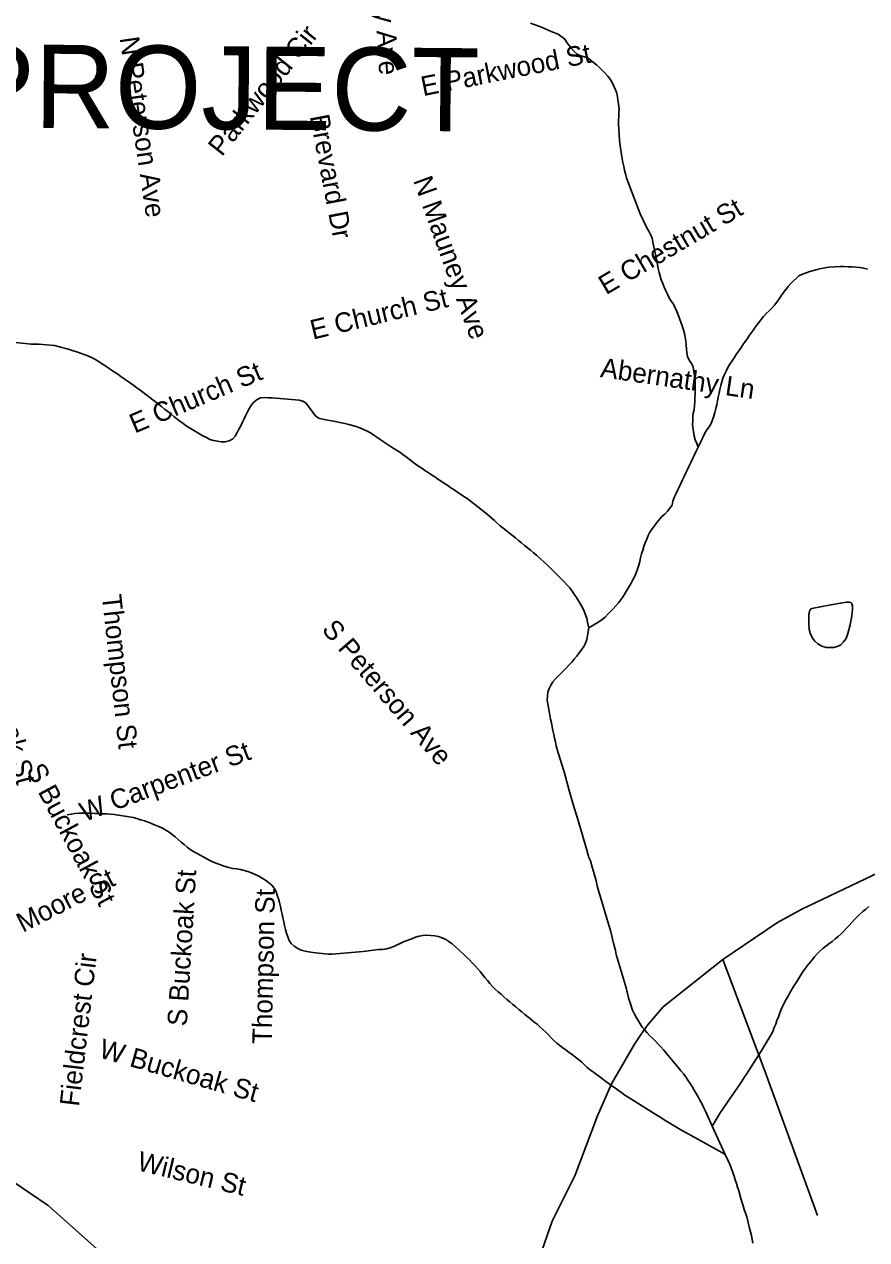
# Model space of a CAD drawing. Extents: x 1379453 to 1387082, y 594364 to 596664.
# Drawn here: x 1380505.6 to 1380647.4, y 596071.5 to 596276.1 of the extents above; entities that cross this region are included whole.
import ezdxf

# ---------------------------------------------------------------- set-up
doc = ezdxf.new("R2010")
doc.units = 0
for name, color, linetype in [('Old_Level_10', 7, 'Continuous'), ('Old_Level_11', 7, 'Continuous'), ('Old_Level_31', 7, 'Continuous'), ('Old_Level_32', 7, 'Continuous'), ('Old_Level_35', 7, 'Continuous'), ('Old_Level_50', 7, 'Continuous'), ('Old_Level_59', 7, 'Continuous'), ('Old_Level_62', 7, 'Continuous')]:
    doc.layers.add(name, color=color, linetype=linetype)

msp = doc.modelspace()

# ---------------------------------------------------------------- linework, layer by layer
at = {"layer": 'Old_Level_31'}
msp.add_line((1380606.68, 596105.29), (1380606.68, 596105.29), dxfattribs=at)
at = {"layer": 'Old_Level_32'}
for points in [[(1380690.45, 596156.89), (1380689.31, 596155.05), (1380687.19, 596153.09), (1380684.16, 596150.95), (1380678.29, 596147.37), (1380650.57, 596133.86), (1380636.43, 596127.15), (1380632.33, 596124.88), (1380623.16, 596118.7), (1380613.12, 596110.73), (1380610.48, 596107.63), (1380609.3, 596105.92)], [(1380609.3, 596105.92), (1380608.29, 596104.44), (1380604.42, 596097.75), (1380602.03, 596092.34), (1380598.21, 596082.26), (1380594.44, 596074.6), (1380592.23, 596068.33)], [(1380520.37, 596067.67), (1380509.57, 596077.25), (1380500.59, 596083.35)]]:
    msp.add_lwpolyline(points, dxfattribs=at)
at = {"layer": 'Old_Level_35'}
msp.add_lwpolyline([(1380639.09, 596075.58), (1380630.27, 596099.77), (1380623.16, 596118.7)], dxfattribs=at)
at = {"layer": 'Old_Level_50'}
msp.add_line((1380609.48, 596106.26), (1380609.48, 596106.26), dxfattribs=at)
at = {"layer": 'Old_Level_59'}
msp.add_line((1380621.38, 596090.59), (1380623.55, 596085.85), dxfattribs=at)
for points in [[(1380600.61, 596174.49), (1380600.37, 596173.19), (1380600.23, 596172.55), (1380600.05, 596171.92), (1380599.74, 596171.34), (1380599.36, 596170.81), (1380598.97, 596170.28), (1380598.57, 596169.76), (1380598.15, 596169.25), (1380597.72, 596168.75), (1380597.29, 596168.26), (1380596.84, 596167.79), (1380596.37, 596167.32), (1380595.91, 596166.85), (1380595.45, 596166.38), (1380595, 596165.91), (1380594.56, 596165.42), (1380594.18, 596164.88), (1380593.9, 596164.29), (1380593.7, 596163.66), (1380593.61, 596163.01), (1380593.59, 596162.35), (1380593.7, 596161.71), (1380594.03, 596159.79), (1380594.15, 596159.14), (1380594.28, 596158.5), (1380594.41, 596157.85), (1380594.55, 596157.21), (1380594.68, 596156.57), (1380594.82, 596155.93), (1380594.97, 596155.29), (1380595.12, 596154.65), (1380595.27, 596154.01), (1380596.04, 596151.5), (1380596.45, 596150.26), (1380597.29, 596147.12), (1380598.02, 596144.6), (1380598.78, 596142.09), (1380599.55, 596139.6), (1380600.24, 596137.09), (1380600.6, 596135.85), (1380600.86, 596135.26), (1380601.22, 596134.02), (1380601.76, 596132.13), (1380602.07, 596130.86), (1380603.18, 596127.09), (1380604.29, 596123.34), (1380604.76, 596121.44), (1380605.07, 596120.18), (1380605.21, 596119.54), (1380606.86, 596113.9), (1380607.33, 596112.02), (1380607.55, 596111.4), (1380607.97, 596110.17), (1380608.25, 596109.58), (1380608.56, 596108.99), (1380608.89, 596108.42), (1380609.22, 596107.86), (1380609.59, 596107.31), (1380610, 596106.8), (1380610.44, 596106.31), (1380610.89, 596105.84), (1380611.35, 596105.37), (1380611.82, 596104.9), (1380612.28, 596104.43), (1380612.73, 596103.96), (1380613.17, 596103.47), (1380615.7, 596100.46), (1380616.11, 596099.96), (1380616.52, 596099.45), (1380616.9, 596098.91), (1380617.28, 596098.37), (1380617.63, 596097.82), (1380617.98, 596097.27), (1380618.32, 596096.7), (1380618.65, 596096.14), (1380618.98, 596095.56), (1380619.3, 596094.99), (1380619.61, 596094.41), (1380619.9, 596093.83), (1380620.18, 596093.24), (1380620.46, 596092.64), (1380621.38, 596090.59)], [(1380623.55, 596085.85), (1380624.1, 596084.66), (1380624.36, 596084.06), (1380624.6, 596083.45), (1380624.82, 596082.83), (1380625.04, 596082.21), (1380625.25, 596081.59), (1380625.46, 596080.96), (1380625.65, 596080.34), (1380625.84, 596079.71), (1380626.18, 596078.46), (1380626.55, 596077.22), (1380626.74, 596076.6), (1380626.99, 596075.98), (1380627.17, 596075.36), (1380627.67, 596073.47), (1380627.83, 596072.84), (1380627.97, 596072.19), (1380628.1, 596071.55), (1380628.22, 596070.9)]]:
    msp.add_lwpolyline(points, dxfattribs=at)
at = {"layer": 'Old_Level_62'}
for points in [[(1380600.49, 596270.38), (1380599.87, 596270.6), (1380599.23, 596270.8), (1380598.64, 596271.09), (1380598.13, 596271.51), (1380597.7, 596272.01), (1380597.29, 596272.52), (1380596.9, 596273.04), (1380596.57, 596273.61), (1380595.41, 596274.42), (1380594.26, 596274.9), (1380592.64, 596275.6), (1380590.8, 596276.31)], [(1380618.98, 596204.89), (1380618.75, 596205.51), (1380618.52, 596206.13), (1380618.34, 596206.75), (1380618.07, 596208.68), (1380618.09, 596209.34), (1380618.12, 596210), (1380618.17, 596210.65), (1380618.34, 596211.28), (1380618.39, 596211.94), (1380618.42, 596212.59), (1380618.45, 596213.25), (1380618.47, 596213.91), (1380618.49, 596214.56), (1380618.49, 596215.22), (1380618.49, 596215.87), (1380618.43, 596216.53), (1380618.17, 596218.44), (1380617.85, 596219), (1380617.49, 596219.57), (1380617.22, 596220.16), (1380617.09, 596220.8), (1380617.02, 596221.45), (1380616.98, 596222.11), (1380616.93, 596222.77), (1380616.83, 596223.42), (1380616.69, 596224.06), (1380616.51, 596224.69), (1380616.32, 596225.32), (1380616.11, 596225.94), (1380615.88, 596226.56), (1380615.65, 596227.18), (1380615.39, 596227.78), (1380615.12, 596228.38), (1380614.84, 596228.97), (1380614.48, 596229.52), (1380614.13, 596230.07), (1380613.83, 596230.66), (1380613.55, 596231.25), (1380613.28, 596231.85), (1380613.03, 596232.46), (1380612.79, 596233.07), (1380612.58, 596233.69), (1380612.41, 596234.33), (1380612.26, 596234.97), (1380612.14, 596235.61), (1380612.02, 596236.26), (1380611.64, 596238.16), (1380611.37, 596239.45), (1380611.23, 596240.09), (1380610.99, 596240.69), (1380610.69, 596241.28), (1380610.36, 596241.86), (1380609.26, 596244.19), (1380607.18, 596249.66), (1380606.96, 596250.27), (1380606.78, 596250.91), (1380606.61, 596251.54), (1380606.46, 596252.18), (1380606.32, 596252.82), (1380606.19, 596253.47), (1380605.82, 596256.03), (1380605.76, 596256.67), (1380605.57, 596259.27), (1380605.59, 596259.92), (1380605.62, 596260.58), (1380605.66, 596261.24), (1380605.68, 596261.89), (1380605.43, 596263.84), (1380605.32, 596264.48), (1380605.1, 596265.09), (1380604.83, 596265.69), (1380604.52, 596266.28), (1380604.18, 596266.84), (1380603.8, 596267.37), (1380603.37, 596267.87), (1380602.9, 596268.33), (1380602.42, 596268.78), (1380601.92, 596269.21), (1380600.49, 596270.38)], [(1380618.98, 596204.89), (1380619.54, 596206.08), (1380619.82, 596206.68), (1380620.11, 596207.26), (1380620.45, 596207.82), (1380620.84, 596208.36), (1380621.17, 596208.92), (1380621.41, 596209.53), (1380621.63, 596210.15), (1380621.82, 596210.78), (1380622, 596211.42), (1380622.15, 596212.05), (1380622.28, 596212.69), (1380622.39, 596213.34), (1380622.51, 596213.99), (1380622.66, 596214.63), (1380622.82, 596215.27), (1380622.98, 596215.91), (1380623.18, 596216.53), (1380623.42, 596217.14), (1380623.7, 596217.73), (1380624.01, 596218.31), (1380624.34, 596218.88), (1380624.7, 596219.44), (1380625.05, 596219.98), (1380625.42, 596220.53), (1380625.79, 596221.07), (1380626.16, 596221.61), (1380626.53, 596222.16), (1380626.91, 596222.7), (1380627.29, 596223.23), (1380627.67, 596223.77), (1380628.05, 596224.3), (1380628.43, 596224.84), (1380628.82, 596225.37), (1380629.2, 596225.9), (1380629.6, 596226.42), (1380629.99, 596226.94), (1380630.44, 596227.43), (1380630.93, 596227.86), (1380631.41, 596228.31), (1380631.83, 596228.81), (1380632.23, 596229.34), (1380632.62, 596229.87), (1380633, 596230.4), (1380633.38, 596230.94), (1380633.77, 596231.46), (1380634.18, 596231.98), (1380634.62, 596232.46), (1380635.95, 596233.75), (1380636.55, 596234.02), (1380637.16, 596234.26), (1380637.78, 596234.49), (1380638.41, 596234.68), (1380639.04, 596234.85), (1380639.69, 596234.99), (1380640.33, 596235.12), (1380640.98, 596235.22), (1380642.93, 596235.32), (1380643.58, 596235.31), (1380644.24, 596235.3), (1380644.9, 596235.28), (1380645.56, 596235.24), (1380646.21, 596235.17), (1380646.86, 596235.06), (1380647.49, 596234.87)], [(1380504.13, 596222.52), (1380506.71, 596222.27), (1380507.37, 596222.25), (1380508.03, 596222.25), (1380508.68, 596222.22), (1380510.62, 596222.01), (1380511.26, 596221.88), (1380511.89, 596221.72), (1380512.52, 596221.55), (1380513.15, 596221.36), (1380513.78, 596221.16), (1380514.4, 596220.96), (1380515.03, 596220.75), (1380515.65, 596220.53), (1380516.26, 596220.28), (1380516.86, 596220.01), (1380517.43, 596219.71), (1380518, 596219.37), (1380518.56, 596219.02), (1380519.1, 596218.66), (1380519.65, 596218.29), (1380520.19, 596217.92), (1380520.74, 596217.55), (1380521.27, 596217.18), (1380521.81, 596216.81), (1380522.35, 596216.43), (1380522.89, 596216.06), (1380523.43, 596215.68), (1380523.97, 596215.3), (1380524.5, 596214.92), (1380525.04, 596214.54), (1380527.64, 596212.56), (1380528.16, 596212.16), (1380528.67, 596211.75), (1380529.18, 596211.34), (1380529.7, 596210.92), (1380530.21, 596210.51), (1380530.72, 596210.1), (1380531.24, 596209.7), (1380531.76, 596209.3), (1380532.28, 596208.9), (1380532.82, 596208.52), (1380533.36, 596208.16), (1380533.92, 596207.82), (1380534.49, 596207.48), (1380535.05, 596207.15), (1380535.63, 596206.83), (1380536.21, 596206.52), (1380536.79, 596206.23), (1380537.42, 596206.02), (1380538.06, 596205.9), (1380538.72, 596205.8), (1380539.37, 596205.82), (1380540.02, 596205.98), (1380540.58, 596206.29), (1380541.03, 596206.79), (1380541.37, 596207.36), (1380541.68, 596207.93), (1380541.98, 596208.52), (1380542.27, 596209.11), (1380542.56, 596209.7), (1380542.85, 596210.29), (1380543.15, 596210.88), (1380543.45, 596211.46), (1380543.78, 596212.02), (1380544.21, 596212.51), (1380544.74, 596212.92), (1380545.34, 596213.2), (1380545.99, 596213.25), (1380546.65, 596213.24), (1380547.3, 596213.21), (1380551.19, 596212.91), (1380551.84, 596212.85), (1380552.47, 596212.65), (1380553.01, 596212.31), (1380553.41, 596211.79), (1380553.79, 596211.25), (1380554.16, 596210.71), (1380554.55, 596210.18), (1380555.08, 596209.79), (1380556.33, 596209.52), (1380557.62, 596209.32), (1380559.53, 596208.92), (1380560.17, 596208.76), (1380560.81, 596208.59), (1380561.43, 596208.38), (1380562.04, 596208.15), (1380562.66, 596207.9), (1380563.25, 596207.63), (1380563.82, 596207.31), (1380564.37, 596206.95), (1380564.92, 596206.58), (1380565.45, 596206.2), (1380567.64, 596204.75), (1380568.21, 596204.42), (1380568.75, 596204.06)], [(1380568.75, 596204.06), (1380569.3, 596203.69), (1380569.83, 596203.31), (1380570.33, 596202.89), (1380570.84, 596202.48), (1380571.38, 596202.11), (1380571.93, 596201.74), (1380572.47, 596201.37), (1380573.01, 596201.01), (1380573.56, 596200.64), (1380574.1, 596200.28), (1380574.65, 596199.92), (1380575.19, 596199.55), (1380575.74, 596199.19), (1380576.29, 596198.82), (1380576.83, 596198.46), (1380577.38, 596198.09), (1380577.92, 596197.72), (1380578.47, 596197.36), (1380579.01, 596196.99), (1380579.55, 596196.62), (1380580.09, 596196.25), (1380580.63, 596195.87), (1380583.2, 596193.84), (1380584.7, 596192.57), (1380585.18, 596192.12), (1380585.69, 596191.7), (1380586.19, 596191.28), (1380586.7, 596190.87), (1380587.21, 596190.45), (1380587.72, 596190.04), (1380588.23, 596189.63), (1380588.75, 596189.21), (1380589.25, 596188.8), (1380589.76, 596188.39), (1380590.27, 596187.97), (1380590.78, 596187.56), (1380591.28, 596187.14), (1380591.78, 596186.71), (1380593.73, 596184.96), (1380596.49, 596182.19), (1380596.94, 596181.71), (1380597.37, 596181.21), (1380597.77, 596180.69), (1380598.15, 596180.15), (1380598.52, 596179.6), (1380598.87, 596179.05), (1380599.21, 596178.49), (1380599.54, 596177.92), (1380599.83, 596177.33), (1380600.06, 596176.72), (1380600.24, 596176.09), (1380600.39, 596175.45), (1380600.61, 596174.49)], [(1380600.61, 596174.49), (1380601.74, 596175.16), (1380602.3, 596175.51), (1380602.82, 596175.89), (1380603.32, 596176.32), (1380603.79, 596176.78), (1380604.26, 596177.25), (1380604.71, 596177.72), (1380605.15, 596178.21), (1380605.56, 596178.72), (1380605.97, 596179.24), (1380606.35, 596179.77), (1380606.7, 596180.33), (1380607.04, 596180.89), (1380607.38, 596181.46), (1380607.7, 596182.03), (1380608.01, 596182.61), (1380608.31, 596183.19), (1380608.57, 596183.79), (1380608.81, 596184.4), (1380608.99, 596185.03), (1380609.16, 596185.67), (1380609.31, 596186.3), (1380609.48, 596186.94), (1380609.66, 596187.57), (1380609.88, 596188.19), (1380610.09, 596188.82), (1380610.33, 596189.44), (1380610.59, 596190.04), (1380610.89, 596190.62), (1380611.24, 596191.17), (1380611.63, 596191.7), (1380612.04, 596192.21), (1380612.89, 596193.22), (1380613.38, 596193.64), (1380613.81, 596194.14), (1380614.22, 596194.66), (1380614.6, 596195.18), (1380614.72, 596195.82), (1380614.97, 596196.42), (1380615.25, 596197.02), (1380615.53, 596197.62), (1380615.81, 596198.21), (1380616.09, 596198.8), (1380616.37, 596199.4), (1380616.65, 596199.99), (1380616.93, 596200.58), (1380617.22, 596201.17), (1380617.5, 596201.77), (1380617.78, 596202.36), (1380618.06, 596202.95), (1380618.34, 596203.54), (1380618.63, 596204.14), (1380618.98, 596204.89)], [(1380638.39, 596177.82), (1380639.59, 596178.05), (1380641.35, 596178.35), (1380643.31, 596178.74), (1380644, 596178.85), (1380644.37, 596178.85), (1380644.68, 596178.75), (1380644.85, 596178.56), (1380644.96, 596178.23), (1380644.97, 596177.67), (1380644.89, 596176.51), (1380644.58, 596175.02), (1380644.21, 596173.53), (1380643.9, 596172.73), (1380643.48, 596172.17), (1380643.04, 596171.67), (1380642.42, 596171.36), (1380641.76, 596171.2), (1380641.17, 596171.17), (1380640.55, 596171.21), (1380639.84, 596171.43), (1380639.15, 596171.81), (1380638.62, 596172.25), (1380638.27, 596172.79), (1380637.91, 596173.5), (1380637.71, 596174.21), (1380637.62, 596175.23), (1380637.66, 596176.68), (1380637.76, 596177.32), (1380637.92, 596177.63), (1380638.11, 596177.77), (1380638.39, 596177.82)], [(1380552.81, 596120.08), (1380552.16, 596120.23), (1380551.59, 596120.54), (1380551.01, 596120.91), (1380550.5, 596121.35), (1380550.14, 596121.88), (1380549.92, 596122.48), (1380549.72, 596123.1), (1380549.54, 596123.73), (1380549.38, 596124.37), (1380549.24, 596125.02), (1380549.1, 596125.67), (1380548.96, 596126.32), (1380548.82, 596126.97), (1380548.67, 596127.62), (1380548.51, 596128.27), (1380548.34, 596128.9), (1380548.14, 596129.52), (1380547.93, 596130.13), (1380547.63, 596130.69), (1380547.2, 596131.18), (1380546.67, 596131.61), (1380546.13, 596132.01), (1380545.59, 596132.39), (1380545.01, 596132.69), (1380544.41, 596132.97), (1380543.81, 596133.24), (1380543.2, 596133.48), (1380542.57, 596133.68), (1380541.94, 596133.84), (1380541.29, 596133.93), (1380540.63, 596134), (1380540, 596134.15), (1380539.36, 596134.35), (1380538.75, 596134.56), (1380538.13, 596134.78), (1380537.51, 596135.02), (1380536.92, 596135.3), (1380534.06, 596136.87), (1380533.5, 596137.21), (1380532.97, 596137.59), (1380532.46, 596138.01), (1380531.96, 596138.44), (1380531.46, 596138.87), (1380530.96, 596139.3), (1380530.45, 596139.71), (1380529.93, 596140.1), (1380529.38, 596140.45), (1380528.8, 596140.76), (1380528.2, 596141.04), (1380527.6, 596141.3), (1380526.99, 596141.56), (1380526.38, 596141.8), (1380525.76, 596142.01), (1380525.13, 596142.21), (1380524.5, 596142.4), (1380523.86, 596142.55), (1380523.22, 596142.67), (1380520.68, 596143.1), (1380520.03, 596143.15), (1380519.37, 596143.19), (1380518.72, 596143.22), (1380518.06, 596143.24), (1380517.4, 596143.26), (1380516.74, 596143.28), (1380516.09, 596143.3), (1380515.43, 596143.3), (1380514.77, 596143.3), (1380514.12, 596143.27), (1380513.47, 596143.16), (1380512.77, 596143.02)], [(1380621.38, 596090.59), (1380622.01, 596091.74), (1380622.34, 596092.3), (1380622.7, 596092.85), (1380623.07, 596093.4), (1380623.44, 596093.94), (1380623.81, 596094.48), (1380624.18, 596095.02), (1380624.55, 596095.56), (1380624.93, 596096.1), (1380625.3, 596096.64), (1380625.68, 596097.18), (1380626.05, 596097.72), (1380626.41, 596098.27), (1380626.77, 596098.82), (1380627.12, 596099.37), (1380629.58, 596103.25), (1380629.93, 596103.8), (1380631.28, 596106.05), (1380631.59, 596106.58), (1380631.82, 596107.2), (1380632.05, 596107.81), (1380632.27, 596108.43), (1380632.5, 596109.05), (1380632.74, 596109.67), (1380632.99, 596110.27), (1380633.26, 596110.87), (1380633.56, 596111.45), (1380633.86, 596112.03), (1380634.19, 596112.6), (1380634.51, 596113.17), (1380634.85, 596113.74), (1380635.19, 596114.3), (1380635.54, 596114.86), (1380636.58, 596116.53), (1380636.96, 596117.07), (1380637.36, 596117.59), (1380638.18, 596118.62), (1380638.59, 596119.13), (1380639.02, 596119.62), (1380639.49, 596120.07), (1380639.99, 596120.5), (1380640.5, 596120.92), (1380641.02, 596121.32), (1380641.54, 596121.72), (1380642.06, 596122.13), (1380642.56, 596122.55), (1380643.05, 596122.99), (1380643.51, 596123.45), (1380643.97, 596123.93), (1380644.41, 596124.41), (1380644.85, 596124.9), (1380645.3, 596125.38), (1380645.76, 596125.86), (1380646.23, 596126.31), (1380646.71, 596126.75), (1380647.22, 596127.16), (1380647.74, 596127.57)], [(1380623.55, 596085.85), (1380622.97, 596086.17), (1380618.96, 596088.42), (1380616.09, 596089.99), (1380615.52, 596090.32), (1380614.96, 596090.67), (1380614.4, 596091.01), (1380613.84, 596091.36), (1380613.28, 596091.7), (1380612.73, 596092.05), (1380612.17, 596092.4), (1380611.62, 596092.75), (1380607.22, 596095.49), (1380606.67, 596095.86), (1380606.14, 596096.23), (1380605.6, 596096.61), (1380605.06, 596096.99), (1380604.54, 596097.37), (1380604, 596097.76), (1380603.47, 596098.15), (1380602.95, 596098.54), (1380602.42, 596098.94), (1380601.89, 596099.33), (1380601.37, 596099.73), (1380600.84, 596100.12), (1380600.32, 596100.52), (1380599.84, 596100.96), (1380599.37, 596101.42), (1380598.87, 596101.85), (1380598.35, 596102.25), (1380597.83, 596102.64), (1380597.29, 596103.02), (1380596.76, 596103.41), (1380596.23, 596103.8), (1380595.71, 596104.2), (1380595.2, 596104.6), (1380594.69, 596105.02), (1380594.23, 596105.49), (1380593.79, 596105.98), (1380593.34, 596106.46), (1380592.86, 596106.91), (1380592.36, 596107.34), (1380591.87, 596107.76), (1380591.36, 596108.18), (1380590.86, 596108.6), (1380590.35, 596109.02), (1380589.84, 596109.43), (1380589.34, 596109.85), (1380588.82, 596110.27), (1380588.32, 596110.69), (1380587.81, 596111.1), (1380587.3, 596111.52), (1380586.8, 596111.95), (1380586.31, 596112.37), (1380585.82, 596112.81), (1380585.33, 596113.25), (1380584.85, 596113.69), (1380584.38, 596114.15), (1380583.95, 596114.64), (1380583.53, 596115.15), (1380583.11, 596115.66), (1380582.7, 596116.17), (1380582.28, 596116.68), (1380581.84, 596117.17), (1380581.4, 596117.65), (1380580.94, 596118.12), (1380580.48, 596118.59), (1380580.02, 596119.05), (1380579.54, 596119.51), (1380578.07, 596120.86), (1380577.57, 596121.29), (1380577.05, 596121.69), (1380576.5, 596122.04), (1380575.92, 596122.31), (1380575.3, 596122.52), (1380574.64, 596122.66), (1380573.97, 596122.74), (1380573.31, 596122.77), (1380572.67, 596122.72), (1380572.03, 596122.6), (1380571.4, 596122.41), (1380570.77, 596122.18), (1380569.53, 596121.71), (1380568.93, 596121.45), (1380568.33, 596121.15), (1380567.74, 596120.87), (1380567.14, 596120.62), (1380566.51, 596120.45), (1380565.86, 596120.37), (1380565.2, 596120.35), (1380562.6, 596120.04), (1380561.94, 596119.96), (1380561.29, 596119.89), (1380560.64, 596119.83), (1380558.02, 596119.62), (1380557.37, 596119.56), (1380556.71, 596119.59), (1380554.11, 596119.86), (1380553.45, 596119.95), (1380552.81, 596120.08)]]:
    msp.add_lwpolyline(points, dxfattribs=at)

# ---------------------------------------------------------------- texts
at = {"layer": 'Old_Level_10'}
for s, height, rotation, p in [('N Mauney Ave', 3.2808, 273.3637, (1380563.63, 596296.2)), ('Parkwood Cir', 3.2808, 51.4686, (1380538.8, 596253.71)), ('N Peterson Ave', 3.2808, 278.381, (1380521.6, 596273.8)), ('E Parkwood St', 3.2808, 11.3145, (1380572.69, 596264)), ('Brevard Dr', 3.281, 280.8047, (1380553.6, 596260.62)), ('N Mauney Ave', 3.2808, 289.8295, (1380570.99, 596249.83)), ('E Chestnut St', 3.2808, 30.5035, (1380603.49, 596230.48)), ('E Church St', 3.2808, 13.5934, (1380554.14, 596223.01)), ('Abernathy Ln', 3.2808, 351.7603, (1380602.42, 596216.74)), ('E Church St', 3.2808, 22.9985, (1380524.14, 596207.19)), ('Thompson St', 3.2808, 276.2758, (1380518.6, 596179.94)), ('S Peterson Ave', 3.2808, 310.6629, (1380555.49, 596174.15)), ('S Buckoak St', 3.2808, 284.7599, (1380497.6, 596173.35)), ('W Carpenter St', 3.2808, 20.5962, (1380515.67, 596141.81)), ('S Buckoak St', 3.2808, 298.1598, (1380505.81, 596150.6)), ('Moore St', 3.281, 27.1655, (1380505.31, 596123.15)), ('S Buckoak St', 3.2808, 86.5197, (1380532.9, 596107.39)), ('Thompson St', 3.2808, 88.7933, (1380547.21, 596104.41)), ('Fieldcrest Cir', 3.2808, 83.2734, (1380514.75, 596093.84)), ('W Buckoak St', 3.2808, 343.9552, (1380517.94, 596102.24)), ('Wilson St', 3.281, 346.3403, (1380524.37, 596083.24))]:
    msp.add_text(s, height=height, rotation=rotation, dxfattribs=at).set_placement(p)
at = {"layer": 'Old_Level_11'}
msp.add_text('PROJECT', height=14, rotation=359.52, dxfattribs=at).set_placement((1380494.75, 596258.79))

doc.saveas('drawing.dxf')
